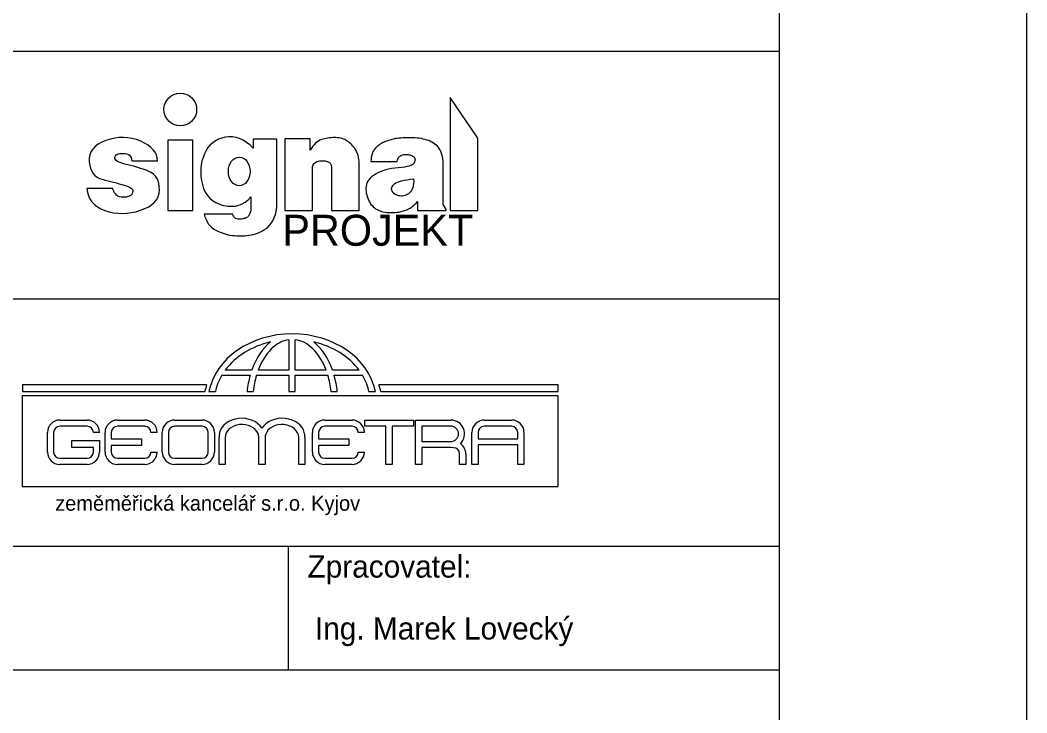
# Model space of a CAD drawing. Extents: x 3181 to 4881, y -1637 to -1193.
# Drawn here: x 4054.2 to 4135.6, y -1538.2 to -1482.2 of the extents above; entities that cross this region are included whole.
import ezdxf

# ---------------------------------------------------------------- set-up
doc = ezdxf.new("R2010")
doc.units = 0
for name, color, linetype in [('Default', 7, 'Continuous'), ('Vrstva 1', 7, 'Continuous'), ('Vrstva 11', 7, 'Continuous'), ('Vrstva 17', 7, 'Continuous'), ('Vrstva 6', 7, 'Continuous')]:
    doc.layers.add(name, color=color, linetype=linetype)

msp = doc.modelspace()

# ---------------------------------------------------------------- linework, layer by layer
at = {"layer": 'Default'}
msp.add_lwpolyline([(3925.563, -1636.746), (4135.563, -1636.746), (4135.563, -1339.746), (3925.563, -1339.746)], close=True, dxfattribs=at)
at = {"layer": 'Vrstva 1'}
msp.add_lwpolyline([(3945.563, -1359.746), (4115.563, -1359.746), (4115.563, -1619.746), (3945.563, -1619.746)], close=True, dxfattribs=at)
at = {"layer": 'Vrstva 11'}
for points in [[(4091.228, -1497.626), (4091.228, -1491.786), (4088.988, -1488.506), (4088.988, -1497.626), (4091.228, -1497.626)], [(4062.499, -1497.86), (4062.861, -1497.844), (4063.228, -1497.796), (4063.599, -1497.717), (4063.975, -1497.607), (4064.329, -1497.471), (4064.637, -1497.315), (4064.898, -1497.139), (4065.112, -1496.943), (4065.28, -1496.727), (4065.4, -1496.491), (4065.474, -1496.235), (4065.5, -1495.959), (4065.49, -1495.685), (4065.451, -1495.437), (4065.385, -1495.212), (4065.291, -1495.013), (4065.17, -1494.838), (4065.021, -1494.688), (4064.844, -1494.563), (4064.639, -1494.462), (4064.42, -1494.376), (4064.198, -1494.294), (4063.973, -1494.217), (4063.747, -1494.144), (4063.518, -1494.075), (4063.287, -1494.011), (4063.054, -1493.952), (4062.818, -1493.896), (4062.596, -1493.841), (4062.405, -1493.782), (4062.244, -1493.719), (4062.114, -1493.652), (4062.014, -1493.581), (4061.945, -1493.506), (4061.906, -1493.427), (4061.897, -1493.343), (4061.914, -1493.264), (4061.95, -1493.195), (4062.006, -1493.137), (4062.082, -1493.09), (4062.178, -1493.053), (4062.294, -1493.028), (4062.429, -1493.013), (4062.585, -1493.01), (4062.74, -1493.021), (4062.875, -1493.05), (4062.99, -1493.097), (4063.085, -1493.163), (4063.16, -1493.247), (4063.214, -1493.349), (4063.249, -1493.469), (4063.263, -1493.608), (4065.342, -1493.608), (4065.323, -1493.366), (4065.261, -1493.136), (4065.156, -1492.919), (4065.008, -1492.715), (4064.817, -1492.523), (4064.583, -1492.345), (4064.307, -1492.179), (4063.987, -1492.025), (4063.645, -1491.896), (4063.3, -1491.801), (4062.952, -1491.741), (4062.602, -1491.717), (4062.249, -1491.727), (4061.894, -1491.771), (4061.535, -1491.851), (4061.174, -1491.966), (4060.836, -1492.108), (4060.547, -1492.271), (4060.306, -1492.454), (4060.114, -1492.658), (4059.971, -1492.882), (4059.876, -1493.127), (4059.83, -1493.393), (4059.832, -1493.679), (4059.872, -1493.96), (4059.938, -1494.212), (4060.03, -1494.434), (4060.148, -1494.627), (4060.293, -1494.791), (4060.464, -1494.924), (4060.661, -1495.029), (4060.885, -1495.103), (4061.12, -1495.163), (4061.351, -1495.223), (4061.578, -1495.282), (4061.802, -1495.341), (4062.023, -1495.4), (4062.239, -1495.458), (4062.452, -1495.516), (4062.662, -1495.574), (4062.854, -1495.634), (4063.016, -1495.698), (4063.146, -1495.767), (4063.246, -1495.841), (4063.314, -1495.918), (4063.352, -1496.001), (4063.359, -1496.088), (4063.335, -1496.179), (4063.289, -1496.267), (4063.228, -1496.343), (4063.152, -1496.408), (4063.062, -1496.461), (4062.958, -1496.503), (4062.84, -1496.533), (4062.707, -1496.551), (4062.559, -1496.558), (4062.411, -1496.547), (4062.275, -1496.514), (4062.152, -1496.458), (4062.04, -1496.38), (4061.942, -1496.279), (4061.855, -1496.155), (4061.781, -1496.008), (4061.72, -1495.84), (4059.639, -1495.84), (4059.683, -1496.147), (4059.767, -1496.429), (4059.89, -1496.687), (4060.052, -1496.92), (4060.254, -1497.13), (4060.496, -1497.315), (4060.778, -1497.476), (4061.099, -1497.613), (4061.442, -1497.722), (4061.79, -1497.799), (4062.142, -1497.846), (4062.499, -1497.86)], [(4068.188, -1497.626), (4068.188, -1491.946), (4066.188, -1491.946), (4066.188, -1497.626), (4068.188, -1497.626)], [(4072.047, -1499.668), (4072.216, -1499.664), (4072.386, -1499.656), (4072.558, -1499.642), (4072.731, -1499.624), (4072.905, -1499.597), (4073.079, -1499.558), (4073.253, -1499.507), (4073.426, -1499.443), (4073.6, -1499.368), (4073.772, -1499.28), (4073.945, -1499.181), (4074.117, -1499.069), (4074.282, -1498.939), (4074.43, -1498.786), (4074.563, -1498.611), (4074.679, -1498.412), (4074.78, -1498.19), (4074.865, -1497.945), (4074.934, -1497.677), (4074.988, -1497.386), (4074.988, -1491.866), (4073.068, -1491.866), (4073.068, -1492.586), (4072.802, -1492.331), (4072.531, -1492.118), (4072.257, -1491.946), (4071.978, -1491.815), (4071.695, -1491.725), (4071.407, -1491.676), (4071.116, -1491.669), (4070.82, -1491.702), (4070.533, -1491.77), (4070.267, -1491.867), (4070.024, -1491.992), (4069.802, -1492.146), (4069.602, -1492.329), (4069.423, -1492.539), (4069.267, -1492.779), (4069.132, -1493.047), (4069.022, -1493.333), (4068.937, -1493.626), (4068.878, -1493.926), (4068.845, -1494.233), (4068.838, -1494.548), (4068.857, -1494.869), (4068.901, -1495.198), (4068.972, -1495.534), (4069.072, -1495.858), (4069.205, -1496.148), (4069.37, -1496.406), (4069.568, -1496.632), (4069.799, -1496.825), (4070.062, -1496.985), (4070.358, -1497.112), (4070.687, -1497.207), (4071.023, -1497.265), (4071.342, -1497.282), (4071.643, -1497.259), (4071.926, -1497.195), (4072.191, -1497.09), (4072.438, -1496.944), (4072.668, -1496.758), (4072.88, -1496.531), (4072.88, -1497.608), (4072.861, -1497.696), (4072.838, -1497.777), (4072.81, -1497.853), (4072.778, -1497.923), (4072.742, -1497.988), (4072.701, -1498.047), (4072.655, -1498.1), (4072.605, -1498.147), (4072.55, -1498.189), (4072.487, -1498.225), (4072.417, -1498.256), (4072.34, -1498.281), (4072.256, -1498.302), (4072.165, -1498.316), (4072.067, -1498.326), (4071.962, -1498.33), (4071.858, -1498.324), (4071.765, -1498.306), (4071.682, -1498.274), (4071.609, -1498.229), (4071.546, -1498.171), (4071.493, -1498.099), (4071.451, -1498.014), (4071.418, -1497.916), (4069.111, -1497.916), (4069.18, -1498.144), (4069.264, -1498.352), (4069.361, -1498.542), (4069.472, -1498.714), (4069.596, -1498.867), (4069.735, -1499), (4069.887, -1499.116), (4070.053, -1499.212), (4070.225, -1499.295), (4070.396, -1499.369), (4070.565, -1499.435), (4070.733, -1499.492), (4070.899, -1499.54), (4071.064, -1499.58), (4071.227, -1499.611), (4071.389, -1499.634), (4071.551, -1499.65), (4071.715, -1499.66), (4071.88, -1499.667), (4072.047, -1499.668)], [(4081.628, -1497.626), (4081.628, -1493.826), (4081.624, -1493.656), (4081.61, -1493.492), (4081.586, -1493.336), (4081.55, -1493.186), (4081.504, -1493.042), (4081.447, -1492.905), (4081.379, -1492.775), (4081.301, -1492.651), (4081.216, -1492.535), (4081.129, -1492.427), (4081.04, -1492.327), (4080.949, -1492.235), (4080.856, -1492.152), (4080.761, -1492.077), (4080.664, -1492.01), (4080.565, -1491.951), (4080.462, -1491.9), (4080.356, -1491.855), (4080.245, -1491.818), (4080.13, -1491.787), (4080.011, -1491.764), (4079.887, -1491.747), (4079.759, -1491.738), (4079.627, -1491.735), (4079.493, -1491.738), (4079.361, -1491.746), (4079.229, -1491.759), (4079.099, -1491.777), (4078.97, -1491.8), (4078.842, -1491.828), (4078.716, -1491.861), (4078.59, -1491.898), (4078.467, -1491.947), (4078.345, -1492.011), (4078.226, -1492.093), (4078.11, -1492.19), (4077.996, -1492.305), (4077.884, -1492.435), (4077.775, -1492.582), (4077.668, -1492.746), (4077.668, -1491.826), (4075.628, -1491.826), (4075.628, -1497.626), (4077.868, -1497.626), (4077.868, -1494.066), (4077.902, -1493.975), (4077.946, -1493.894), (4078.001, -1493.823), (4078.065, -1493.762), (4078.139, -1493.711), (4078.223, -1493.67), (4078.317, -1493.639), (4078.421, -1493.617), (4078.527, -1493.604), (4078.628, -1493.598), (4078.723, -1493.597), (4078.814, -1493.602), (4078.899, -1493.614), (4078.978, -1493.631), (4079.053, -1493.655), (4079.122, -1493.685), (4079.184, -1493.719), (4079.238, -1493.758), (4079.284, -1493.8), (4079.321, -1493.846), (4079.35, -1493.895), (4079.371, -1493.948), (4079.383, -1494.005), (4079.388, -1494.066), (4079.388, -1497.626), (4081.628, -1497.626)], [(4084.19, -1497.79), (4084.352, -1497.787), (4084.51, -1497.778), (4084.663, -1497.764), (4084.812, -1497.744), (4084.956, -1497.718), (4085.097, -1497.686), (4085.233, -1497.649), (4085.364, -1497.606), (4085.493, -1497.555), (4085.62, -1497.493), (4085.746, -1497.421), (4085.869, -1497.339), (4085.991, -1497.246), (4086.112, -1497.143), (4086.23, -1497.03), (4086.348, -1496.906), (4086.348, -1497.626), (4088.668, -1497.626), (4088.668, -1497.546), (4088.428, -1497.146), (4088.428, -1493.666), (4088.401, -1493.461), (4088.365, -1493.271), (4088.32, -1493.095), (4088.265, -1492.934), (4088.201, -1492.787), (4088.127, -1492.655), (4088.043, -1492.537), (4087.95, -1492.434), (4087.849, -1492.341), (4087.742, -1492.255), (4087.628, -1492.176), (4087.508, -1492.104), (4087.382, -1492.039), (4087.25, -1491.981), (4087.111, -1491.93), (4086.966, -1491.886), (4086.814, -1491.848), (4086.655, -1491.816), (4086.489, -1491.79), (4086.315, -1491.769), (4086.135, -1491.754), (4085.947, -1491.744), (4085.751, -1491.741), (4085.549, -1491.743), (4085.35, -1491.749), (4085.166, -1491.757), (4084.997, -1491.768), (4084.843, -1491.78), (4084.703, -1491.795), (4084.578, -1491.813), (4084.467, -1491.832), (4084.372, -1491.854), (4084.283, -1491.877), (4084.194, -1491.903), (4084.104, -1491.931), (4084.013, -1491.96), (4083.921, -1491.992), (4083.829, -1492.025), (4083.737, -1492.061), (4083.643, -1492.098), (4083.55, -1492.14), (4083.458, -1492.188), (4083.366, -1492.244), (4083.276, -1492.306), (4083.187, -1492.375), (4083.099, -1492.451), (4083.012, -1492.533), (4082.926, -1492.623), (4082.845, -1492.72), (4082.776, -1492.827), (4082.718, -1492.944), (4082.67, -1493.069), (4082.633, -1493.204), (4082.607, -1493.349), (4082.592, -1493.502), (4082.588, -1493.666), (4084.708, -1493.666), (4084.723, -1493.569), (4084.747, -1493.482), (4084.78, -1493.404), (4084.821, -1493.335), (4084.872, -1493.275), (4084.93, -1493.225), (4084.998, -1493.183), (4085.073, -1493.151), (4085.154, -1493.127), (4085.235, -1493.109), (4085.317, -1493.098), (4085.399, -1493.093), (4085.481, -1493.095), (4085.565, -1493.103), (4085.648, -1493.118), (4085.732, -1493.139), (4085.813, -1493.165), (4085.884, -1493.192), (4085.947, -1493.222), (4086, -1493.254), (4086.045, -1493.288), (4086.082, -1493.325), (4086.109, -1493.363), (4086.128, -1493.404), (4086.14, -1493.447), (4086.145, -1493.493), (4086.144, -1493.541), (4086.136, -1493.592), (4086.122, -1493.647), (4086.103, -1493.704), (4086.076, -1493.763), (4086.044, -1493.826), (4085.993, -1493.887), (4085.912, -1493.943), (4085.801, -1493.994), (4085.659, -1494.039), (4085.487, -1494.079), (4085.285, -1494.114), (4085.052, -1494.143), (4084.789, -1494.168), (4084.517, -1494.194), (4084.258, -1494.232), (4084.01, -1494.28), (4083.775, -1494.338), (4083.553, -1494.407), (4083.342, -1494.486), (4083.144, -1494.577), (4082.958, -1494.677), (4082.789, -1494.785), (4082.641, -1494.898), (4082.513, -1495.015), (4082.407, -1495.137), (4082.321, -1495.263), (4082.256, -1495.394), (4082.212, -1495.529), (4082.189, -1495.669), (4082.181, -1495.81), (4082.182, -1495.95), (4082.192, -1496.089), (4082.211, -1496.227), (4082.239, -1496.364), (4082.276, -1496.499), (4082.322, -1496.634), (4082.377, -1496.767), (4082.44, -1496.895), (4082.51, -1497.014), (4082.587, -1497.124), (4082.671, -1497.226), (4082.761, -1497.319), (4082.859, -1497.402), (4082.964, -1497.477), (4083.075, -1497.543), (4083.193, -1497.601), (4083.317, -1497.651), (4083.447, -1497.693), (4083.584, -1497.728), (4083.726, -1497.755), (4083.875, -1497.774), (4084.03, -1497.786), (4084.19, -1497.79)], [(4084.906, -1496.445), (4084.803, -1496.425), (4084.708, -1496.396), (4084.622, -1496.36), (4084.543, -1496.317), (4084.472, -1496.266), (4084.409, -1496.206), (4084.354, -1496.14), (4084.307, -1496.065), (4084.273, -1495.987), (4084.255, -1495.911), (4084.254, -1495.835), (4084.27, -1495.759), (4084.302, -1495.685), (4084.351, -1495.612), (4084.417, -1495.54), (4084.5, -1495.468), (4084.603, -1495.4), (4084.732, -1495.337), (4084.886, -1495.279), (4085.065, -1495.227), (4085.269, -1495.18), (4085.498, -1495.138), (4085.753, -1495.101), (4086.032, -1495.07), (4086.037, -1495.268), (4086.028, -1495.45), (4086.006, -1495.616), (4085.972, -1495.766), (4085.924, -1495.9), (4085.864, -1496.017), (4085.79, -1496.119), (4085.704, -1496.204), (4085.611, -1496.275), (4085.515, -1496.334), (4085.418, -1496.382), (4085.319, -1496.418), (4085.219, -1496.442), (4085.116, -1496.455), (4085.012, -1496.456), (4084.906, -1496.445)]]:
    msp.add_lwpolyline(points, dxfattribs=at)
msp.add_circle((4067.188, -1489.466), 1.32, dxfattribs=at)
msp.add_ellipse((4071.948, -1494.466), major_axis=(0, 1.16), ratio=0.758621, dxfattribs=at)
at = {"layer": 'Vrstva 17'}
for p, q in [((4075.958, -1508.059), (4075.958, -1510.505)), ((4076.465, -1510.505), (4076.465, -1508.057)), ((4072.965, -1510.505), (4070.82, -1510.505)), ((4075.958, -1510.505), (4073.482, -1510.505)), ((4078.96, -1510.505), (4076.465, -1510.505)), ((4081.622, -1510.505), (4079.477, -1510.505)), ((4070.545, -1510.916), (4072.832, -1510.916)), ((4073.342, -1510.916), (4075.958, -1510.916)), ((4075.958, -1510.916), (4075.958, -1512.237)), ((4076.465, -1512.237), (4076.465, -1510.916)), ((4076.465, -1510.916), (4079.099, -1510.916)), ((4079.609, -1510.916), (4081.897, -1510.916)), ((4069.314, -1511.706), (4054.433, -1511.706)), ((4054.433, -1511.706), (4054.433, -1512.237)), ((4054.433, -1512.237), (4069.176, -1512.237)), ((4069.502, -1512.237), (4070.019, -1512.237)), ((4072.575, -1512.237), (4073.075, -1512.237)), ((4075.958, -1512.237), (4076.465, -1512.237)), ((4079.366, -1512.237), (4079.866, -1512.237)), ((4082.423, -1512.237), (4082.94, -1512.237)), ((4097.712, -1511.706), (4083.233, -1511.706)), ((4083.371, -1512.237), (4097.712, -1512.237)), ((4097.712, -1512.237), (4097.712, -1511.706)), ((4097.71, -1512.581), (4054.427, -1512.581)), ((4054.427, -1512.581), (4054.427, -1519.919)), ((4097.71, -1519.919), (4097.71, -1512.581)), ((4057.452, -1514.547), (4059.663, -1514.547)), ((4062.108, -1514.547), (4064.319, -1514.547)), ((4066.732, -1514.547), (4068.943, -1514.547)), ((4078.851, -1514.547), (4081.061, -1514.547)), ((4086.188, -1514.547), (4089.032, -1514.547)), ((4091.736, -1514.547), (4093.947, -1514.547)), ((4056.454, -1517.131), (4056.454, -1515.545)), ((4056.953, -1515.545), (4056.953, -1517.131)), ((4059.663, -1515.046), (4057.452, -1515.046)), ((4060.66, -1515.545), (4060.162, -1515.545)), ((4061.11, -1517.131), (4061.11, -1515.545)), ((4061.609, -1515.545), (4061.609, -1516.056)), ((4064.319, -1515.046), (4062.108, -1515.046)), ((4065.317, -1515.545), (4064.818, -1515.545)), ((4065.734, -1517.131), (4065.734, -1515.545)), ((4066.233, -1515.545), (4066.233, -1517.131)), ((4068.943, -1515.046), (4066.732, -1515.046)), ((4069.442, -1517.131), (4069.442, -1515.545)), ((4069.941, -1515.545), (4069.941, -1517.131)), ((4077.853, -1517.131), (4077.853, -1515.545)), ((4078.352, -1515.545), (4078.352, -1516.056)), ((4081.061, -1515.046), (4078.851, -1515.046)), ((4082.059, -1515.545), (4081.56, -1515.545)), ((4083.794, -1518.129), (4083.794, -1515.034)), ((4084.297, -1515.034), (4084.297, -1518.129)), ((4089.032, -1515.036), (4086.692, -1515.036)), ((4086.692, -1515.036), (4086.692, -1516.286)), ((4090.738, -1518.129), (4090.738, -1515.545)), ((4091.237, -1515.545), (4091.237, -1516.054)), ((4093.947, -1515.046), (4091.736, -1515.046)), ((4094.446, -1516.054), (4094.446, -1515.545)), ((4094.945, -1515.545), (4094.945, -1518.129)), ((4058.427, -1516.753), (4058.427, -1516.208)), ((4058.427, -1516.208), (4060.66, -1516.208)), ((4060.66, -1516.208), (4060.66, -1517.131)), ((4061.609, -1516.056), (4064.052, -1516.056)), ((4064.052, -1516.056), (4064.052, -1516.6)), ((4070.313, -1518.129), (4070.313, -1515.944)), ((4070.814, -1515.944), (4070.814, -1518.129)), ((4073.533, -1518.129), (4073.533, -1515.944)), ((4074.033, -1515.944), (4074.033, -1518.129)), ((4076.752, -1518.129), (4076.752, -1515.944)), ((4077.253, -1515.944), (4077.253, -1518.129)), ((4078.352, -1516.056), (4080.795, -1516.056)), ((4080.795, -1516.056), (4080.795, -1516.6)), ((4086.692, -1516.286), (4089.032, -1516.286)), ((4091.237, -1516.054), (4094.446, -1516.054)), ((4060.162, -1516.753), (4058.427, -1516.753)), ((4060.162, -1517.131), (4060.162, -1516.753)), ((4064.052, -1516.6), (4061.609, -1516.6)), ((4061.609, -1516.6), (4061.609, -1517.131)), ((4064.818, -1517.131), (4065.317, -1517.131)), ((4080.795, -1516.6), (4078.352, -1516.6)), ((4078.352, -1516.6), (4078.352, -1517.131)), ((4081.56, -1517.131), (4082.059, -1517.131)), ((4089.032, -1516.775), (4086.692, -1516.775)), ((4089.247, -1516.779), (4089.032, -1516.775)), ((4089.746, -1518.129), (4089.746, -1517.278)), ((4090.244, -1517.278), (4090.244, -1518.129)), ((4094.446, -1516.557), (4091.237, -1516.557)), ((4091.237, -1516.557), (4091.237, -1518.129)), ((4094.446, -1518.129), (4094.446, -1516.557)), ((4057.452, -1517.63), (4059.663, -1517.63)), ((4062.108, -1517.63), (4064.319, -1517.63)), ((4066.732, -1517.63), (4068.943, -1517.63)), ((4078.851, -1517.63), (4081.061, -1517.63)), ((4059.663, -1518.129), (4057.452, -1518.129)), ((4064.319, -1518.129), (4062.108, -1518.129)), ((4068.943, -1518.129), (4066.732, -1518.129)), ((4070.814, -1518.129), (4070.313, -1518.129)), ((4074.033, -1518.129), (4073.533, -1518.129)), ((4077.253, -1518.129), (4076.752, -1518.129)), ((4081.061, -1518.129), (4078.851, -1518.129)), ((4084.297, -1518.129), (4083.794, -1518.129)), ((4090.244, -1518.129), (4089.746, -1518.129)), ((4091.237, -1518.129), (4090.738, -1518.129)), ((4094.945, -1518.129), (4094.446, -1518.129)), ((4054.427, -1519.919), (4097.71, -1519.919))]:
    msp.add_line(p, q, dxfattribs=at)
for points in [[(4083.794, -1515.034), (4082.096, -1515.034), (4082.096, -1514.547), (4086.009, -1514.547)], [(4086.009, -1514.547), (4086.009, -1515.034), (4084.297, -1515.034)], [(4086.692, -1516.775), (4086.692, -1518.129), (4086.188, -1518.129), (4086.188, -1514.547)]]:
    msp.add_lwpolyline(points, dxfattribs=at)
for centre, radius, start, end in [((4057.452, -1515.545), 0.998, 90, 180), ((4059.663, -1515.545), 0.998, 360, 90), ((4062.108, -1515.545), 0.998, 90, 180), ((4064.319, -1515.545), 0.998, 360, 90), ((4066.732, -1515.545), 0.998, 90, 180), ((4068.943, -1515.545), 0.998, 360, 90), ((4078.851, -1515.545), 0.998, 90, 180), ((4081.061, -1515.545), 0.998, 360, 90), ((4089.032, -1515.661), 1.114, 314.45734, 90), ((4091.736, -1515.545), 0.998, 90, 180), ((4093.947, -1515.545), 0.998, 360, 90), ((4057.452, -1515.545), 0.499, 90, 180), ((4059.663, -1515.545), 0.499, 0, 90), ((4062.108, -1515.545), 0.499, 90, 180), ((4064.319, -1515.545), 0.499, 0, 90), ((4066.732, -1515.545), 0.499, 90, 180), ((4068.943, -1515.545), 0.499, 0, 90), ((4072.25, -1515.994), 1.938, 166.96576, 178.52091), ((4072.579, -1516.009), 0.957, 3.86486, 22.41569), ((4075.315, -1515.994), 1.938, 1.47909, 13.03424), ((4078.851, -1515.545), 0.499, 90, 180), ((4081.061, -1515.545), 0.499, 0, 90), ((4089.032, -1515.661), 0.625, 270, 90), ((4091.736, -1515.545), 0.499, 90, 180), ((4093.947, -1515.545), 0.499, 0, 90), ((4075.266, -1516.066), 1.238, 162.61388, 174.3506), ((4089.247, -1517.278), 0.998, 360, 55.44734), ((4057.452, -1517.131), 0.998, 180, 270), ((4057.452, -1517.131), 0.499, 180, 270), ((4059.663, -1517.131), 0.998, 270, 0), ((4059.663, -1517.131), 0.499, 270, 0), ((4062.108, -1517.131), 0.998, 180, 270), ((4062.108, -1517.131), 0.499, 180, 270), ((4064.319, -1517.131), 0.998, 270, 0), ((4064.319, -1517.131), 0.499, 270, 0), ((4066.732, -1517.131), 0.998, 180, 270), ((4066.732, -1517.131), 0.499, 180, 270), ((4068.943, -1517.131), 0.998, 270, 0), ((4068.943, -1517.131), 0.499, 270, 0), ((4078.851, -1517.131), 0.998, 180, 270), ((4078.851, -1517.131), 0.499, 180, 270), ((4081.061, -1517.131), 0.998, 270, 0), ((4081.061, -1517.131), 0.499, 270, 0), ((4089.247, -1517.278), 0.499, 0, 90)]:
    msp.add_arc(centre, radius, start, end, dxfattribs=at)
for centre, major_axis, ratio, start_param, end_param in [((4076.221, -1513.109), (-6.804, 0), 0.811768, 3.300239, 6.124539), ((4076.221, -1513.109), (-6.296, 0), 0.804826, 4.992897, 5.743383), ((4076.221, -1513.109), (0, 5.524), 0.668443, 0.491666, 1.079789), ((4076.221, -1513.109), (0, 5.067), 0.630136, 0.08224, 1.030995), ((4076.221, -1513.109), (0, 5.067), 0.630136, 5.252191, 6.206521), ((4076.221, -1513.109), (0, 5.524), 0.668443, 5.203397, 5.79152), ((4076.221, -1513.109), (-6.296, 0), 0.804826, 3.681394, 4.431881), ((4076.221, -1513.109), (-6.296, 0), 0.804826, 5.835664, 6.110118), ((4076.221, -1513.109), (0, 5.524), 0.668443, 1.16256, 1.41215), ((4076.221, -1513.109), (0, 5.067), 0.630136, 1.123275, 1.397729), ((4076.221, -1513.109), (0, 5.067), 0.630136, 4.885456, 5.159911), ((4076.221, -1513.109), (0, 5.524), 0.668443, 4.871035, 5.120625), ((4076.221, -1513.109), (-6.296, 0), 0.804826, 3.31466, 3.589114), ((4075.895, -1513.109), (-6.804, 0), 0.811768, 6.026233, 6.124539), ((4076.653, -1513.109), (-6.804, 0), 0.811768, 3.300239, 3.398545), ((4072.142, -1515.789), (1.805, 0), 0.766187, 0.429647, 2.97338), ((4072.167, -1515.944), (1.354, 0), 0.766187, 0.29376, 3.141593), ((4075.424, -1515.789), (-1.805, 0), 0.766187, 3.309805, 5.853538), ((4075.398, -1515.944), (-1.354, 0), 0.766187, 3.141593, 6.041607)]:
    msp.add_ellipse(centre, major_axis=major_axis, ratio=ratio, start_param=start_param, end_param=end_param, dxfattribs=at)
at = {"layer": 'Vrstva 6'}
for p, q in [((3945.563, -1504.746), (4115.563, -1504.746)), ((3945.563, -1524.746), (4115.563, -1524.746)), ((4075.913, -1534.746), (4075.913, -1524.746))]:
    msp.add_line(p, q, dxfattribs=at)
msp.add_lwpolyline([(3945.563, -1484.746), (4115.563, -1484.746), (4115.563, -1534.746), (3945.563, -1534.746)], close=True, dxfattribs=at)

# ---------------------------------------------------------------- texts
at = {"layer": 'Vrstva 11'}
msp.add_text('PROJEKT', height=2.5, dxfattribs=at).set_placement((4075.428, -1500.469))
at = {"layer": 'Vrstva 17'}
msp.add_text('zeměměřická kancelář s.r.o. Kyjov', height=1.20984, dxfattribs=at).set_placement((4057.079, -1521.868))
at = {"layer": 'Vrstva 6'}
for s, p in [('Zpracovatel:', (4077.459, -1527.273)), ('Ing. Marek Lovecký', (4078.06, -1532.273))]:
    msp.add_text(s, height=1.8, dxfattribs=at).set_placement(p)

doc.saveas('drawing.dxf')
